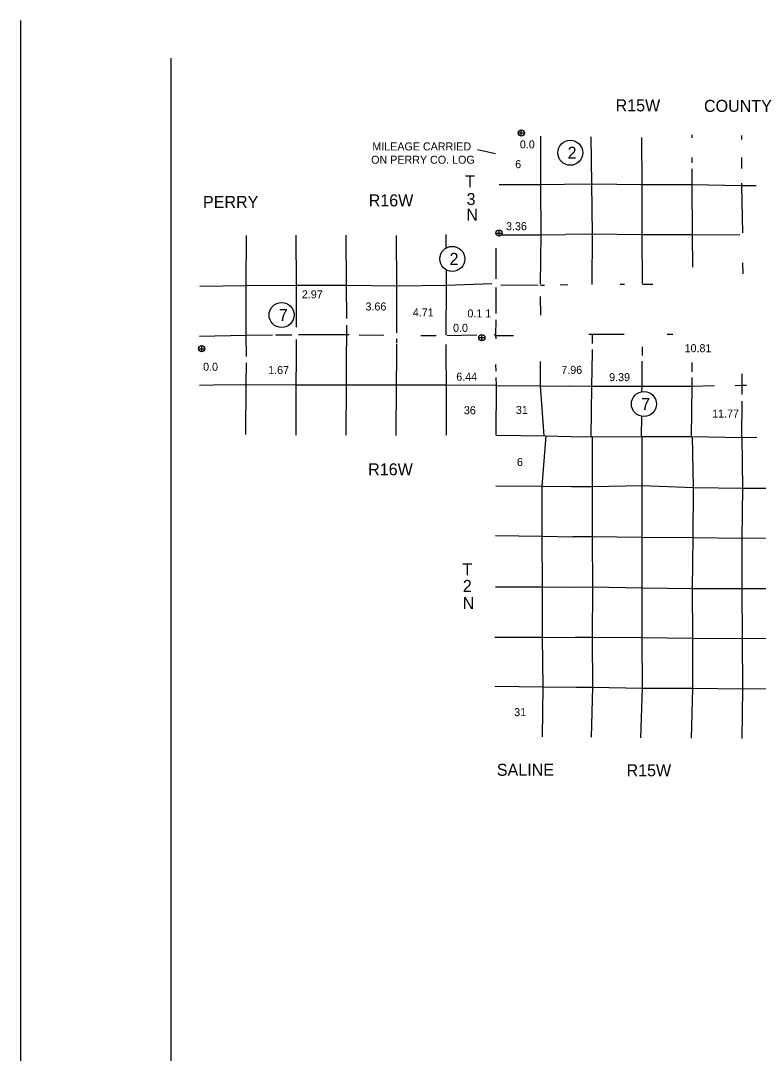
# Model space of a CAD drawing. Extents: x 1127717 to 1741049, y 2026793 to 2244711.
# Drawn here: x 1127717 to 1147166, y 2120236 to 2147475 of the extents above; entities that cross this region are included whole.
import ezdxf

# ---------------------------------------------------------------- set-up
doc = ezdxf.new("R2010")
doc.units = 0
for name, color, linetype in [('25', 7, 'Continuous'), ('26', 7, 'Continuous'), ('27', 7, 'Continuous'), ('30', 7, 'Continuous'), ('4', 7, 'Continuous'), ('5', 7, 'Continuous'), ('58', 7, 'Continuous')]:
    doc.layers.add(name, color=color, linetype=linetype)

msp = doc.modelspace()

# ---------------------------------------------------------------- linework, layer by layer
at = {"layer": '26'}
for p, q in [((1140917, 2144431), (1140917, 2144594)), ((1140836, 2144513), (1140998, 2144513)), ((1140247, 2141870), (1140410, 2141870)), ((1140329, 2141788), (1140329, 2141951)), ((1139795, 2139117), (1139958, 2139117)), ((1139876, 2139036), (1139876, 2139198)), ((1132410, 2138822), (1132572, 2138822)), ((1132491, 2138741), (1132491, 2138903))]:
    msp.add_line(p, q, dxfattribs=at)
for centre in [(1140917, 2144513), (1140329, 2141870), (1139876, 2139117), (1132491, 2138822)]:
    msp.add_circle(centre, 81.2, dxfattribs=at)
at = {"layer": '27'}
msp.add_line((1139764, 2144076), (1140240, 2143967), dxfattribs=at)
for centre in [(1142208, 2143990), (1139097, 2141191), (1134595, 2139712), (1144149, 2137363)]:
    msp.add_circle(centre, 330, dxfattribs=at)
at = {"layer": '30'}
for p, q in [((1127717, 2102595), (1127717, 2147475)), ((1127717, 2147475), (1127717, 2147475)), ((1131677, 2146485), (1131677, 2146485)), ((1131677, 2146485), (1131677, 2103915))]:
    msp.add_line(p, q, dxfattribs=at)
at = {"layer": '4'}
for points in [[(1140244, 2141474), (1140243, 2140663)], [(1140243, 2140437), (1140242, 2139753)], [(1140241, 2139581), (1140240, 2139176), (1140241, 2139085)], [(1140251, 2138227), (1140248, 2138404)], [(1140252, 2136543), (1140259, 2137855), (1140255, 2138060)], [(1140252, 2136543), (1141551, 2136522), (1142211, 2136510)], [(1142211, 2136510), (1142771, 2136501), (1144094, 2136502), (1145412, 2136503), (1146740, 2136484), (1147125, 2136486)]]:
    msp.add_lwpolyline(points, dxfattribs=at)
at = {"layer": '5'}
for points in [[(1141427, 2144429), (1141425, 2143148), (1141433, 2141829), (1141412, 2140520)], [(1142753, 2144407), (1142771, 2143168), (1142782, 2141845), (1142780, 2140522), (1142780, 2140518)], [(1144086, 2144397), (1144097, 2143156), (1144098, 2141828), (1144100, 2140540)], [(1145417, 2144462), (1145417, 2144383)], [(1146725, 2144449), (1146725, 2144344)], [(1145417, 2143869), (1145417, 2143724)], [(1146724, 2143869), (1146724, 2143575)], [(1145417, 2143569), (1145417, 2143160), (1145419, 2141823), (1145429, 2140970)], [(1140329, 2143152), (1141427, 2143151), (1142053, 2143158)], [(1142053, 2143158), (1142773, 2143169), (1144097, 2143156), (1145416, 2143157), (1146722, 2143130), (1147106, 2143125)], [(1146724, 2143185), (1146724, 2143131), (1146749, 2141880)], [(1133661, 2141812), (1133656, 2140493), (1133654, 2139173), (1133661, 2138613)], [(1134969, 2141814), (1134979, 2140498), (1134979, 2139389)], [(1136289, 2141813), (1136299, 2140500), (1136305, 2139620)], [(1137616, 2141810), (1137628, 2140481), (1137629, 2139238)], [(1138931, 2141836), (1138931, 2141482)], [(1140399, 2141829), (1141432, 2141829), (1142083, 2141836)], [(1146678, 2141813), (1145418, 2141823), (1144098, 2141828), (1142781, 2141847), (1142083, 2141836)], [(1146753, 2141083), (1146755, 2140798)], [(1138932, 2140906), (1138932, 2140499), (1138925, 2139177)], [(1132444, 2140469), (1133658, 2140493), (1134979, 2140498), (1136299, 2140501), (1137628, 2140481), (1138934, 2140498), (1140144, 2140542)], [(1140379, 2140511), (1141362, 2140500)], [(1141423, 2140500), (1141526, 2140502)], [(1141941, 2140509), (1142144, 2140513)], [(1143519, 2140526), (1143641, 2140527)], [(1144108, 2140528), (1144381, 2140526)], [(1141416, 2140199), (1141422, 2139706)], [(1136306, 2139445), (1136308, 2139192), (1136301, 2138583)], [(1134353, 2139179), (1133655, 2139174), (1132428, 2139141)], [(1134863, 2139183), (1134439, 2139180)], [(1136382, 2139189), (1136308, 2139191), (1135041, 2139185)], [(1137288, 2139168), (1136645, 2139183)], [(1137628, 2139081), (1137627, 2138964)], [(1138676, 2139164), (1138272, 2139162)], [(1139743, 2139182), (1138965, 2139165)], [(1140240, 2139192), (1140201, 2139192)], [(1140240, 2139168), (1140709, 2139171)], [(1143625, 2139199), (1142780, 2139199), (1142696, 2139197)], [(1142781, 2139215), (1142781, 2139199), (1142784, 2138963)], [(1144912, 2139193), (1144763, 2139194)], [(1134979, 2139068), (1134977, 2138550)], [(1137627, 2138938), (1137623, 2138612)], [(1138926, 2138933), (1138927, 2138643)], [(1142786, 2138804), (1142787, 2138731)], [(1144100, 2138872), (1144101, 2138762)], [(1134977, 2138550), (1134973, 2137866), (1134972, 2136538)], [(1136301, 2138583), (1136298, 2137864), (1136291, 2136537)], [(1137623, 2138612), (1137620, 2137865), (1137610, 2136536)], [(1138927, 2138643), (1138938, 2137866), (1138933, 2136540)], [(1142787, 2138731), (1142767, 2137828), (1142750, 2136501)], [(1144101, 2138762), (1144100, 2138646)], [(1133661, 2138450), (1133652, 2137877), (1133649, 2136562)], [(1141417, 2138482), (1141410, 2137844), (1141507, 2136522)], [(1144098, 2138490), (1144092, 2137828), (1144090, 2137682)], [(1145417, 2138461), (1145415, 2138214)], [(1145413, 2138062), (1145410, 2137829), (1145392, 2136503)], [(1146735, 2138157), (1146734, 2137851), (1146732, 2137614)], [(1132429, 2137864), (1132802, 2137866)], [(1132802, 2137866), (1133652, 2137874), (1134973, 2137865), (1136299, 2137865), (1137619, 2137865), (1138939, 2137866), (1140259, 2137863)], [(1140259, 2137848), (1141412, 2137846), (1142182, 2137837)], [(1146008, 2137839), (1145404, 2137829), (1144086, 2137829), (1142763, 2137829), (1142182, 2137837)], [(1146855, 2137852), (1146729, 2137850), (1146557, 2137847)], [(1146730, 2137435), (1146723, 2136484)], [(1144085, 2137042), (1144081, 2136502)], [(1141561, 2136521), (1141461, 2135195), (1141461, 2133873), (1141464, 2132537), (1141469, 2131214), (1141482, 2129903), (1141463, 2128588)], [(1142783, 2136501), (1142787, 2135184), (1142789, 2133855), (1142790, 2132534), (1142785, 2131200), (1142793, 2129887), (1142763, 2128577)], [(1144070, 2128561), (1144110, 2129872), (1144106, 2131196), (1144106, 2132520), (1144106, 2133846), (1144104, 2135218), (1144104, 2136502)], [(1145426, 2136503), (1145451, 2135165), (1145437, 2133830), (1145422, 2132497), (1145428, 2131176), (1145432, 2129863), (1145396, 2128552)], [(1146738, 2128541), (1146756, 2129850), (1146748, 2131174), (1146744, 2132496), (1146736, 2133819), (1146760, 2135148), (1146744, 2136484)], [(1140247, 2135203), (1141463, 2135194), (1142244, 2135187)], [(1142244, 2135187), (1142789, 2135183), (1144105, 2135213), (1145455, 2135165), (1146764, 2135145), (1147667, 2135144)], [(1140239, 2133894), (1141463, 2133875), (1142277, 2133862)], [(1148078, 2133834), (1146733, 2133815), (1145435, 2133830), (1144103, 2133844), (1142788, 2133856), (1142277, 2133862)], [(1140232, 2132537), (1141464, 2132537), (1142306, 2132533)], [(1142306, 2132533), (1142789, 2132537), (1144104, 2132515), (1145423, 2132499), (1146747, 2132495), (1148082, 2132501)], [(1140222, 2131214), (1141469, 2131215), (1142338, 2131205)], [(1148082, 2131187), (1146745, 2131173), (1145426, 2131180), (1144105, 2131195), (1142783, 2131203), (1142338, 2131205)], [(1140218, 2129917), (1141482, 2129905), (1142370, 2129895)], [(1142370, 2129895), (1142795, 2129891), (1144110, 2129870), (1145431, 2129867), (1146756, 2129849), (1148077, 2129861)]]:
    msp.add_lwpolyline(points, dxfattribs=at)

# ---------------------------------------------------------------- texts
at = {"layer": '25'}
for s, p in [('0.0', (1140879, 2144106)), ('3.36', (1140514, 2141948)), ('0.0', (1139117, 2139265)), ('0.0', (1132527, 2138240))]:
    msp.add_text(s, height=211.2, dxfattribs=at).set_placement(p)
at = {"layer": '27'}
for s, height, p in [('2', 317, (1142137, 2143832)), ('ON PERRY CO. LOG', 211.2, (1136958, 2143701)), ('2', 317, (1139026, 2141033)), ('7', 317, (1134524, 2139554)), ('7', 317, (1144078, 2137205))]:
    msp.add_text(s, height=height, dxfattribs=at).set_placement(p)
at = {"layer": '30'}
for s, height, p in [('R15W', 316.8, (1143403, 2145082)), ('COUNTY', 316.8, (1145734, 2145068)), ('MILEAGE CARRIED ', 211.2, (1136989, 2144052)), ('T', 317, (1139435, 2143076)), ('R16W', 316.8, (1136893, 2142576)), ('3', 317, (1139473, 2142611)), ('PERRY', 316.8, (1132524, 2142534)), ('N', 317, (1139467, 2142203)), ('R16W', 316.8, (1136879, 2135482)), ('T', 317, (1139365, 2132842)), ('2', 317, (1139375, 2132406)), ('N', 317, (1139369, 2131956)), ('SALINE', 316.8, (1140272, 2127557)), ('R15W', 316.8, (1143691, 2127543))]:
    msp.add_text(s, height=height, dxfattribs=at).set_placement(p)
at = {"layer": '5'}
for s, height, p in [('6', 211, (1140755, 2143584)), ('36', 211.2, (1139402, 2137093)), ('31', 211.2, (1140774, 2137101)), ('6', 211, (1140802, 2135729)), ('31', 211.2, (1140730, 2129130))]:
    msp.add_text(s, height=height, dxfattribs=at).set_placement(p)
at = {"layer": '58'}
for s, p in [('2.97', (1135131, 2140150)), ('3.66', (1136809, 2139830)), ('4.71', (1138056, 2139674)), ('0.1 1', (1139496, 2139648)), ('10.81', (1145222, 2138730)), ('1.67', (1134243, 2138153)), ('7.96', (1141972, 2138158)), ('6.44', (1139202, 2137978)), ('9.39', (1143234, 2137966)), ('11.77', (1145949, 2137005))]:
    msp.add_text(s, height=211.2, dxfattribs=at).set_placement(p)

doc.saveas('drawing.dxf')
